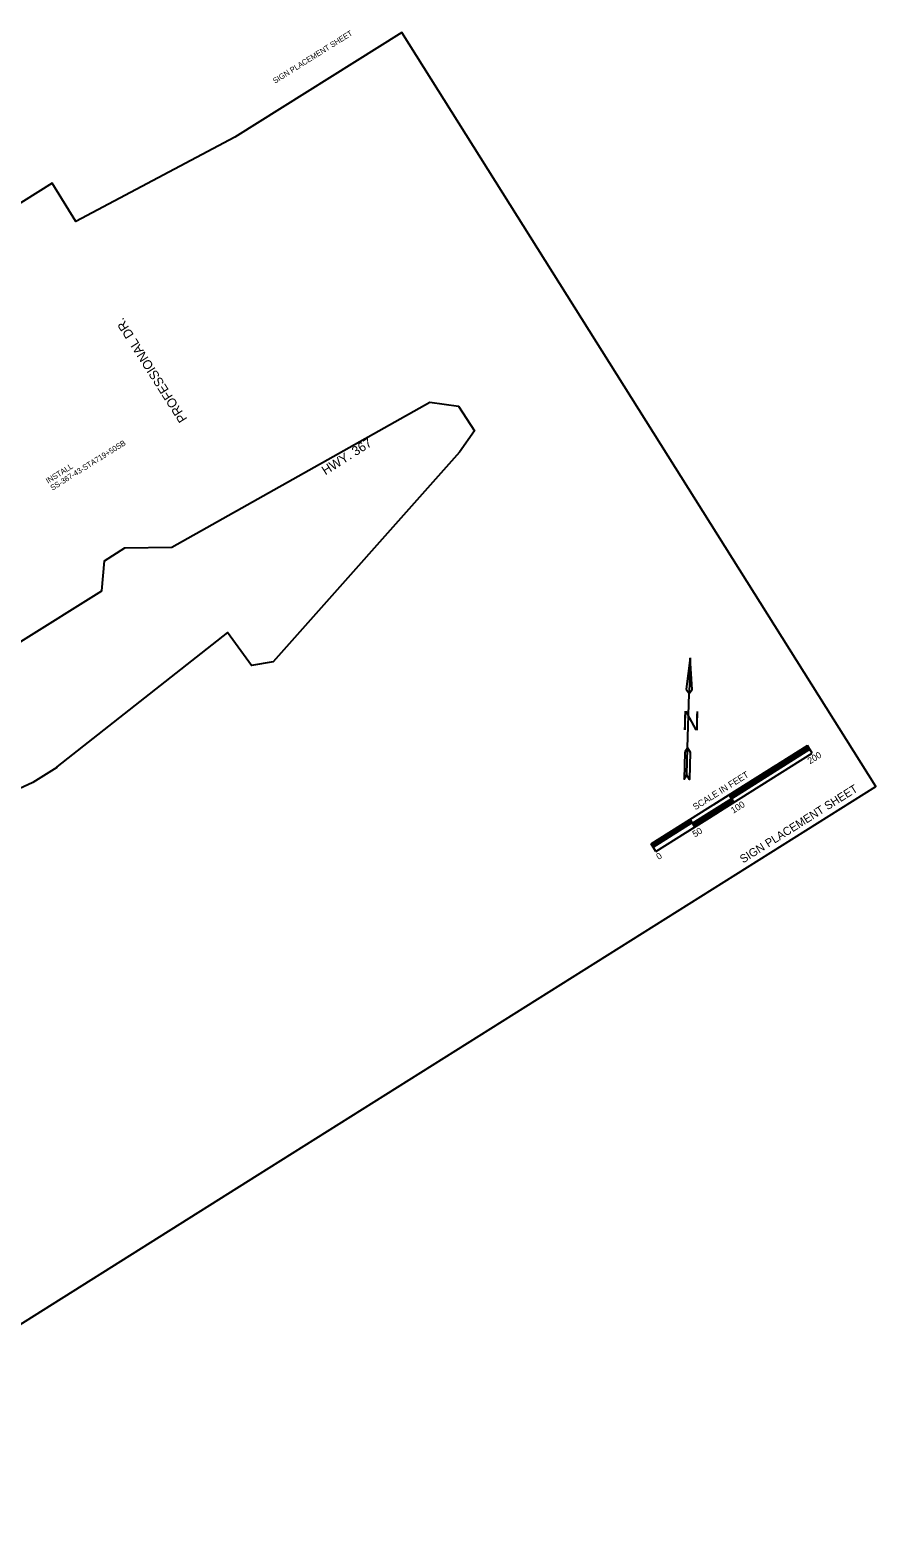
# Model space of a CAD drawing. Extents: x 1289840 to 1295530, y 220865 to 226414.
# Drawn here: x 1294615 to 1295530, y 223034 to 224666 of the extents above; entities that cross this region are included whole.
import ezdxf

# ---------------------------------------------------------------- set-up
doc = ezdxf.new("R2010")
doc.units = 0
for name, color, linetype in [('level 1050', 7, 'Continuous'), ('Plan Text', 7, 'Continuous'), ('R_Border', 7, 'Continuous'), ('R_No Plot', 7, 'Continuous'), ('S_SIGN', 7, 'Continuous'), ('SIGN CALLOUTS', 7, 'Continuous'), ('SIGN STRUC', 7, 'Continuous')]:
    doc.layers.add(name, color=color, linetype=linetype)

msp = doc.modelspace()

# ---------------------------------------------------------------- linework, layer by layer
at = {"layer": 'Plan Text'}
for p, q in [((1295329, 223986.4), (1295324.9, 223952.4)), ((1295324.9, 223952.4), (1295328, 223947.8)), ((1295326.4, 223889), (1295328, 223947.9))]:
    msp.add_line(p, q, dxfattribs=at)
for points in [[(1295329, 223986.2), (1295328, 223947.8), (1295331.2, 223952.3)], [(1295323.3, 223884.4), (1295322.6, 223855), (1295325.6, 223859.8), (1295326.4, 223889)], [(1295326.4, 223889), (1295329.1, 223884.3), (1295328.3, 223854.8), (1295325.6, 223859.8)]]:
    msp.add_lwpolyline(points, close=True, dxfattribs=at)
at = {"layer": 'R_No Plot'}
msp.add_lwpolyline([(1294860.8, 223426.4), (1295530.1, 223847), (1295017.1, 224663.4), (1294836.3, 224549.8), (1294664.4, 224458.8), (1294638.5, 224500), (1293902.2, 224038.1), (1293908.6, 223889.6), (1293972.2, 223777.9), (1294013, 223716.4), (1293913.3, 223586.2), (1293881.3, 223612.6), (1293848.7, 223650.5), (1293977.8, 223445), (1294028.2, 223364.9), (1294086.1, 223400.4), (1294236.2, 223033.9), (1294513, 223207.9)], close=True, dxfattribs=at)
msp.add_lwpolyline([(1294604.6, 224004.1), (1294692.5, 224059.1), (1294695.3, 224091.3), (1294717.2, 224105.3), (1294768.2, 224106.1), (1295047.3, 224263.2), (1295078.4, 224258.8), (1295095.6, 224232), (1295079.5, 224209), (1294878, 223982), (1294854.3, 223978.1), (1294828.6, 224013.9), (1294643.6, 223868.4), (1294643.7, 223867.8), (1294617.9, 223851.4), (1294603.1, 223844.8)], dxfattribs=at)
at = {"layer": 'SIGN CALLOUTS'}
for p, q in [((1295354.6, 223827.6), (1295456.2, 223891.4)), ((1295461.3, 223883.3), (1295456.2, 223891.4)), ((1295292, 223776.9), (1295461.3, 223883.3)), ((1295371.9, 223837.5), (1295456.6, 223890.7)), ((1295372.4, 223836.8), (1295457, 223890.1)), ((1295372.8, 223836.2), (1295457.4, 223889.4)), ((1295373.2, 223835.5), (1295457.9, 223888.7)), ((1295373.6, 223834.8), (1295458.3, 223888)), ((1295374.1, 223834.1), (1295458.7, 223887.4)), ((1295286.8, 223785), (1295422.3, 223870.1)), ((1295374.1, 223834.1), (1295424.9, 223866.1)), ((1295331.7, 223807.5), (1295374.1, 223834.1)), ((1295332.2, 223806.8), (1295374.5, 223833.5)), ((1295332.6, 223806.2), (1295374.9, 223832.8)), ((1295333, 223805.5), (1295375.3, 223832.1)), ((1295333.4, 223804.8), (1295375.8, 223831.4)), ((1295333.9, 223804.1), (1295376.2, 223830.8)), ((1295376.6, 223830.1), (1295371.5, 223838.2)), ((1295287.3, 223784.3), (1295329.6, 223810.9)), ((1295287.7, 223783.6), (1295330, 223810.2)), ((1295288.1, 223782.9), (1295330.5, 223809.6)), ((1295325.8, 223798.1), (1295359.7, 223819.4)), ((1295334.3, 223803.5), (1295329.2, 223811.6)), ((1295286.8, 223785), (1295320.7, 223806.3)), ((1295288.6, 223782.3), (1295330.9, 223808.9)), ((1295289, 223781.6), (1295331.3, 223808.2)), ((1295292, 223776.9), (1295286.8, 223785))]:
    msp.add_line(p, q, dxfattribs=at)

# ---------------------------------------------------------------- texts
at = {"layer": 'level 1050'}
for s, p in [('SS-367-43-STA719+50SB', (1294639, 224167.2)), ('INSTALL', (1294634.2, 224174.8))]:
    msp.add_text(s, height=6, rotation=32.1185, dxfattribs=at).set_placement(p)
at = {"layer": 'Plan Text'}
msp.add_text('N', height=20.4, rotation=358.4728, dxfattribs=at).set_placement((1295320, 223908.5))
at = {"layer": 'R_Border'}
msp.add_text('SIGN PLACEMENT SHEET', height=6, rotation=32.1452, dxfattribs=at).set_placement((1294879.8, 224607.7))
at = {"layer": 'S_SIGN'}
msp.add_text('SIGN PLACEMENT SHEET', height=8.87, rotation=32.1434, dxfattribs=at).set_placement((1295386.4, 223763.8))
at = {"layer": 'SIGN CALLOUTS'}
for s, height, p in [('200', 7, (1295458.9, 223871.1)), ('SCALE IN FEET', 7.001, (1295334.8, 223821.3)), ('100', 7, (1295375.9, 223817.6)), ('50', 7, (1295334.3, 223791.9)), ('0', 7, (1295295.1, 223767.5))]:
    msp.add_text(s, height=height, rotation=32.1572, dxfattribs=at).set_placement(p)
at = {"layer": 'SIGN STRUC'}
for s, rotation, p in [('PROFESSIONAL DR.', 122.43, (1294785.2, 224245)), ('HWY. 367', 32.43, (1294934.4, 224183.8))]:
    msp.add_text(s, height=10, rotation=rotation, dxfattribs=at).set_placement(p)

doc.saveas('drawing.dxf')
